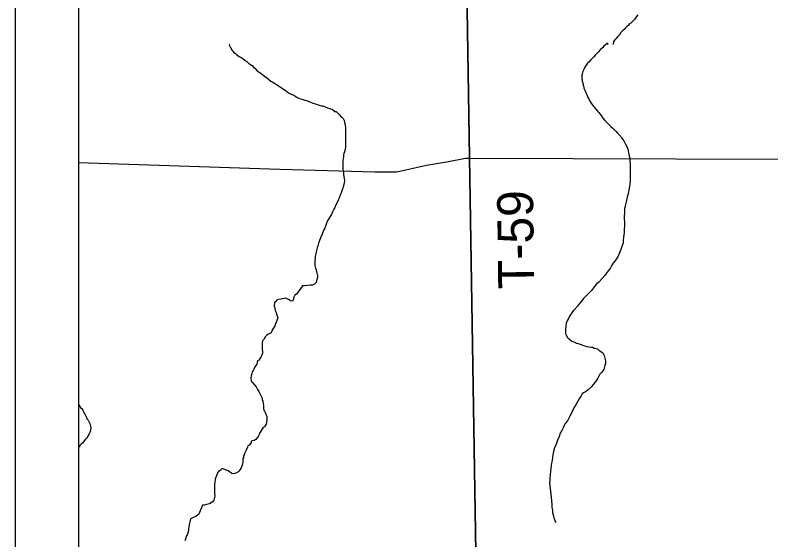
# Model space of a CAD drawing. Extents: x 0 to 34, y 0 to 22.
# Drawn here: x 2 to 3.195, y 17.112 to 17.941 of the extents above; entities that cross this region are included whole.
import ezdxf

# ---------------------------------------------------------------- set-up
doc = ezdxf.new("R2010")
doc.units = 0
for name, color, linetype in [('GM_X_Corporation', 7, 'Continuous'), ('GM_X_Minor_River', 7, 'Continuous'), ('GM_X_Township_Road', 7, 'Continuous'), ('GM_X_Township_Road_Text', 7, 'Continuous'), ('GM_X_US_Route', 7, 'Continuous'), ('SH_Data', 7, 'Continuous')]:
    doc.layers.add(name, color=color, linetype=linetype)

msp = doc.modelspace()

# ---------------------------------------------------------------- linework, layer by layer
at = {"layer": 'GM_X_Corporation'}
for points in [[(3.1996, 20.2345), (3.1561, 20.2337), (3.1064, 20.2336), (3.0286, 20.2331), (3.0007, 20.2328), (2.9354, 20.2326), (2.8825, 20.2322), (2.8234, 20.2319), (2.7333, 20.2317), (2.6825, 20.2316), (2.6344, 20.2324), (2.5847, 20.2334), (2.535, 20.2346), (2.5164, 20.2351), (2.4604, 20.2364), (2.3921, 20.2383), (2.333, 20.2398), (2.2833, 20.2411), (2.246, 20.2419), (2.187, 20.2434), (2.1124, 20.2453), (2.1, 20.2456), (2.1, 14.1)], [(3.1996, 20.2345), (3.1561, 20.2337), (3.1064, 20.2336), (3.0286, 20.2331), (3.0007, 20.2328), (2.9354, 20.2326), (2.8825, 20.2322), (2.8234, 20.2319), (2.7333, 20.2317), (2.6825, 20.2316), (2.6883, 19.5017), (2.7024, 18.7188), (2.7184, 17.7156), (2.7304, 16.9599), (2.7477, 15.8824), (2.7366, 15.2014)]]:
    msp.add_lwpolyline(points, dxfattribs=at)
msp.add_lwpolyline([(2.1, 20.2456), (2.1, 15.2121), (2.7366, 15.2014), (2.7477, 15.8824), (2.7304, 16.9599), (2.7184, 17.7156), (2.7024, 18.7188), (2.6883, 19.5017), (2.6825, 20.2316), (2.6344, 20.2324), (2.5847, 20.2334), (2.535, 20.2346), (2.5164, 20.2351), (2.4604, 20.2364), (2.3921, 20.2383), (2.333, 20.2398), (2.2833, 20.2411), (2.246, 20.2419), (2.187, 20.2434), (2.1124, 20.2453)], close=True, dxfattribs=at)
at = {"layer": 'GM_X_Minor_River'}
for points in [[(2.9845, 17.9415), (2.9822, 17.9384), (2.9791, 17.9339), (2.9757, 17.9301), (2.9734, 17.9282), (2.9715, 17.927), (2.9693, 17.9244), (2.9666, 17.9221), (2.9647, 17.9206), (2.9632, 17.9187), (2.9605, 17.9164), (2.9578, 17.9134), (2.9552, 17.9099), (2.9529, 17.9069), (2.9499, 17.9035), (2.9483, 17.9016), (2.9461, 17.8989), (2.9453, 17.8942)], [(2.3393, 17.8938), (2.3386, 17.8937), (2.3404, 17.8895), (2.3431, 17.8849), (2.3457, 17.8818), (2.3483, 17.8803), (2.3502, 17.8787), (2.3543, 17.8756), (2.3574, 17.8737), (2.36, 17.8722), (2.363, 17.8695), (2.3664, 17.8675), (2.369, 17.8648), (2.3721, 17.8629), (2.3747, 17.861), (2.3769, 17.8587), (2.3792, 17.8571), (2.3826, 17.8529), (2.386, 17.8509), (2.3886, 17.849), (2.3909, 17.8471), (2.3939, 17.8448), (2.3973, 17.8421), (2.4007, 17.8394), (2.4041, 17.8367), (2.4075, 17.8347), (2.4101, 17.8332), (2.4131, 17.8312), (2.4165, 17.8293), (2.4271, 17.8223), (2.432, 17.8181), (2.4373, 17.8154), (2.4407, 17.8142), (2.4437, 17.8122), (2.4459, 17.8107), (2.4497, 17.8091), (2.4531, 17.808), (2.4565, 17.8068), (2.4615, 17.8052), (2.466, 17.8036), (2.4709, 17.8017), (2.4762, 17.8001), (2.4808, 17.7985), (2.4842, 17.7977), (2.4865, 17.7973), (2.4914, 17.7953), (2.4952, 17.7938), (2.4986, 17.793), (2.5012, 17.7922), (2.5057, 17.7887), (2.5076, 17.7883), (2.5103, 17.786), (2.5129, 17.7833), (2.5144, 17.7814), (2.5163, 17.7798), (2.5185, 17.7775), (2.52, 17.7741), (2.5207, 17.7714), (2.5215, 17.7695), (2.5218, 17.7661), (2.5222, 17.7638), (2.5225, 17.7585), (2.5225, 17.7558), (2.5224, 17.7524), (2.5223, 17.7471), (2.5223, 17.7421), (2.5222, 17.7372), (2.5222, 17.733), (2.5217, 17.7285), (2.5209, 17.7247), (2.5198, 17.7224), (2.5194, 17.7201), (2.5189, 17.7171), (2.5185, 17.714), (2.5181, 17.7114), (2.5181, 17.7076), (2.518, 17.7046), (2.518, 17.7007), (2.5183, 17.6988), (2.5183, 17.6969), (2.5187, 17.6947), (2.519, 17.6916), (2.5194, 17.6886), (2.5197, 17.6859), (2.5204, 17.6829), (2.5208, 17.6802), (2.5208, 17.6783), (2.5204, 17.676), (2.5199, 17.6734), (2.5188, 17.6696), (2.518, 17.6673), (2.5172, 17.665), (2.516, 17.6616), (2.5148, 17.6586), (2.5137, 17.6563), (2.5129, 17.6544), (2.5121, 17.6518), (2.5105, 17.6484), (2.509, 17.645), (2.507, 17.6408), (2.5054, 17.637)], [(2.937, 17.8942), (2.937, 17.8972), (2.9355, 17.8954), (2.9332, 17.8939), (2.9305, 17.8916), (2.9285, 17.8894), (2.9251, 17.886), (2.9224, 17.8826), (2.9197, 17.88), (2.917, 17.8773), (2.9147, 17.8747), (2.9124, 17.8721), (2.9097, 17.8694), (2.9074, 17.8672), (2.9051, 17.8649), (2.9027, 17.8619), (2.9016, 17.86), (2.8996, 17.857), (2.8989, 17.8547), (2.8977, 17.8517), (2.8969, 17.8494), (2.8961, 17.8457), (2.8961, 17.843), (2.896, 17.8403), (2.8964, 17.8384), (2.8967, 17.8361), (2.8978, 17.8323), (2.8982, 17.8297), (2.8989, 17.8274), (2.8993, 17.8255), (2.9004, 17.8224), (2.9041, 17.8136), (2.9056, 17.8106), (2.907, 17.8083), (2.9085, 17.8048), (2.9119, 17.8002), (2.9153, 17.7952), (2.9186, 17.7918), (2.9209, 17.7891), (2.9228, 17.7868), (2.9246, 17.7849), (2.9265, 17.7822), (2.9291, 17.778), (2.9325, 17.7745), (2.9355, 17.7711), (2.9381, 17.7687), (2.9419, 17.7649), (2.9453, 17.7618), (2.9479, 17.7591), (2.9501, 17.7568), (2.9524, 17.7541), (2.9554, 17.7511), (2.9577, 17.7488), (2.9588, 17.7468), (2.9606, 17.7445), (2.9621, 17.7422), (2.9633, 17.7403), (2.9647, 17.7369), (2.967, 17.7334), (2.9677, 17.7315), (2.9684, 17.7289), (2.9692, 17.7266), (2.9695, 17.7239), (2.9703, 17.7216), (2.971, 17.7182), (2.9717, 17.7151), (2.972, 17.7125), (2.972, 17.7102), (2.9723, 17.7056), (2.9723, 17.7007), (2.9721, 17.6897), (2.9721, 17.6859), (2.9724, 17.6828), (2.9724, 17.6786), (2.972, 17.6741), (2.9715, 17.6699), (2.9703, 17.665), (2.9695, 17.6608), (2.9687, 17.6566), (2.9675, 17.6532), (2.9663, 17.6479), (2.9655, 17.6437), (2.9643, 17.6396), (2.9639, 17.6369), (2.9635, 17.635), (2.9635, 17.632), (2.9634, 17.6274), (2.963, 17.6236), (2.963, 17.6206), (2.9629, 17.6172), (2.9633, 17.6153), (2.9632, 17.6122), (2.9632, 17.6092), (2.9632, 17.6069), (2.9631, 17.6039), (2.9627, 17.6012), (2.9627, 17.597), (2.9623, 17.5936), (2.9618, 17.5898), (2.9614, 17.5849), (2.961, 17.5807)], [(2.5054, 17.637), (2.5039, 17.6344), (2.5019, 17.6302), (2.5, 17.6257), (2.4946, 17.617), (2.4934, 17.6148), (2.4922, 17.6121), (2.491, 17.6083), (2.4895, 17.6042), (2.4879, 17.6015), (2.4867, 17.5977), (2.4848, 17.5939), (2.4832, 17.5898), (2.4812, 17.5845), (2.4797, 17.5803), (2.4785, 17.5765), (2.4773, 17.5731), (2.4765, 17.569), (2.4757, 17.5659), (2.4753, 17.564), (2.4749, 17.5621), (2.4745, 17.5595), (2.4741, 17.5564), (2.474, 17.5526), (2.4736, 17.5496), (2.4736, 17.5473), (2.4739, 17.5454), (2.4743, 17.5431), (2.475, 17.5408), (2.4757, 17.5382), (2.4765, 17.5359), (2.4772, 17.5332), (2.4776, 17.5309), (2.4779, 17.5286), (2.4779, 17.5264), (2.4771, 17.523), (2.4767, 17.5211), (2.4759, 17.5184), (2.4732, 17.5158), (2.4701, 17.5143), (2.4667, 17.514), (2.4621, 17.5136), (2.4576, 17.5129), (2.4545, 17.513), (2.4449, 17.5001), (2.4422, 17.4983), (2.4406, 17.4953), (2.4402, 17.4934), (2.4394, 17.4907), (2.4383, 17.4888), (2.4356, 17.4892), (2.4322, 17.4912), (2.4292, 17.4931), (2.4273, 17.4935), (2.4208, 17.4921), (2.4163, 17.4914), (2.414, 17.491), (2.4128, 17.4884), (2.4101, 17.4865), (2.4097, 17.4808), (2.4104, 17.4785), (2.4108, 17.4766), (2.4111, 17.4747), (2.4119, 17.4728), (2.4126, 17.4709), (2.4133, 17.4686), (2.4144, 17.4659), (2.4152, 17.4625), (2.414, 17.4583), (2.4128, 17.4553), (2.4116, 17.4534), (2.4104, 17.45), (2.4077, 17.4455), (2.4062, 17.4432), (2.4046, 17.4387), (2.4004, 17.4368), (2.3981, 17.4349), (2.3958, 17.4331), (2.3931, 17.4282), (2.3911, 17.4259), (2.3903, 17.4229), (2.3903, 17.4206), (2.3903, 17.4164), (2.3906, 17.4141), (2.3906, 17.4122), (2.3913, 17.4095), (2.3909, 17.4069), (2.3901, 17.4035), (2.3886, 17.4005), (2.387, 17.3978), (2.3851, 17.3956), (2.3832, 17.3944), (2.382, 17.3895), (2.3792, 17.385), (2.3773, 17.3816), (2.3761, 17.3793), (2.375, 17.3771), (2.3742, 17.374), (2.3734, 17.371), (2.3726, 17.3676), (2.3733, 17.3626)], [(2.961, 17.5807), (2.9602, 17.578), (2.9594, 17.5758), (2.9582, 17.572), (2.9566, 17.5678), (2.9551, 17.564), (2.9527, 17.5591), (2.95, 17.5554), (2.9481, 17.552), (2.9457, 17.5489), (2.9434, 17.5459), (2.9411, 17.5414), (2.938, 17.5373), (2.9353, 17.5339), (2.9322, 17.5293), (2.928, 17.5244), (2.923, 17.5188), (2.9184, 17.5154), (2.9156, 17.5113), (2.9118, 17.5064), (2.8979, 17.4925), (2.8952, 17.4887), (2.8921, 17.485), (2.889, 17.4808), (2.8844, 17.4759), (2.8821, 17.4733), (2.8802, 17.4703), (2.8783, 17.4684), (2.8763, 17.465), (2.8747, 17.4612), (2.8732, 17.459), (2.8712, 17.454), (2.8704, 17.4487), (2.87, 17.4453), (2.87, 17.443), (2.8699, 17.44), (2.8703, 17.4377), (2.871, 17.4354), (2.8729, 17.432), (2.8744, 17.4301), (2.8763, 17.4289), (2.88, 17.4258), (2.8831, 17.4246), (2.8857, 17.4235), (2.8876, 17.4227), (2.8902, 17.4219), (2.8925, 17.4211), (2.8948, 17.4203), (2.8971, 17.4191), (2.9001, 17.4183), (2.9039, 17.4172), (2.9077, 17.4164), (2.9111, 17.4159), (2.9134, 17.4159), (2.9156, 17.4147), (2.9187, 17.4139), (2.9206, 17.4135), (2.9228, 17.4116), (2.9292, 17.407), (2.9314, 17.4028), (2.9325, 17.3989), (2.9333, 17.3948), (2.9332, 17.3925), (2.9332, 17.3898), (2.9324, 17.3872), (2.9308, 17.3807), (2.9269, 17.3762), (2.9243, 17.3736), (2.9211, 17.3672), (2.9173, 17.3615), (2.9138, 17.3574), (2.9111, 17.3536), (2.9053, 17.3483), (2.9015, 17.3457), (2.8988, 17.3439), (2.8965, 17.3424), (2.8942, 17.3382), (2.8919, 17.3344), (2.8895, 17.331), (2.8872, 17.3261), (2.8845, 17.3216), (2.8822, 17.3182), (2.8802, 17.3129), (2.8767, 17.3069), (2.8732, 17.2997), (2.8697, 17.2955), (2.8682, 17.2921), (2.8662, 17.2884), (2.8643, 17.2846), (2.8619, 17.2804), (2.86, 17.2751), (2.8576, 17.2691), (2.8553, 17.263), (2.8529, 17.2573), (2.8513, 17.2513), (2.8501, 17.246), (2.8493, 17.2418), (2.8489, 17.2369), (2.8481, 17.2327), (2.8476, 17.2293), (2.8459, 17.2149)], [(2.3733, 17.3626), (2.3748, 17.3607), (2.3774, 17.3576), (2.3812, 17.3534), (2.383, 17.3492), (2.3852, 17.3461), (2.3864, 17.3438), (2.3878, 17.3408), (2.389, 17.3385), (2.3904, 17.3354), (2.3908, 17.3335), (2.3915, 17.3309), (2.3922, 17.3274), (2.3926, 17.3236), (2.3926, 17.3213), (2.3929, 17.3187), (2.3933, 17.3168), (2.394, 17.3149), (2.3955, 17.3129), (2.397, 17.3091), (2.3977, 17.3068), (2.3981, 17.3049), (2.398, 17.3004), (2.3968, 17.2947), (2.3941, 17.2905), (2.3922, 17.2894), (2.3864, 17.28), (2.3856, 17.2781), (2.3844, 17.2751), (2.3821, 17.2721), (2.3805, 17.2702), (2.3779, 17.2687), (2.3752, 17.268), (2.3733, 17.2676), (2.3732, 17.2649), (2.3702, 17.2612), (2.3679, 17.2601), (2.3675, 17.2582), (2.3655, 17.2532), (2.3632, 17.2491), (2.362, 17.2461), (2.3612, 17.2442), (2.3608, 17.2415), (2.36, 17.2396), (2.36, 17.2354), (2.3595, 17.2313), (2.3576, 17.2252), (2.3556, 17.2229), (2.3537, 17.2203), (2.3522, 17.2184), (2.3502, 17.2173), (2.3472, 17.2166), (2.3449, 17.2162), (2.3426, 17.2163), (2.337, 17.2205), (2.3324, 17.2225), (2.3287, 17.224), (2.3268, 17.224), (2.3244, 17.2214), (2.3214, 17.2199), (2.3198, 17.2177), (2.3183, 17.2127), (2.3171, 17.2105), (2.3163, 17.2074), (2.3155, 17.2025), (2.3151, 17.1999), (2.315, 17.198), (2.315, 17.1953), (2.3153, 17.1915), (2.3153, 17.1888), (2.3153, 17.185), (2.3156, 17.1808), (2.3144, 17.1744), (2.3117, 17.171), (2.3071, 17.1688), (2.3025, 17.1673), (2.2987, 17.1666), (2.296, 17.1663), (2.2902, 17.1523), (2.2882, 17.1508), (2.2848, 17.1478), (2.2794, 17.1459), (2.2771, 17.1448), (2.2763, 17.1403), (2.2755, 17.138), (2.2747, 17.1323), (2.2743, 17.1289), (2.2739, 17.1262), (2.2723, 17.1205), (2.2711, 17.1179), (2.2695, 17.1126), (2.2684, 17.1103)], [(2.1, 17.3262), (2.1025, 17.3225), (2.1036, 17.3206), (2.1063, 17.3179), (2.107, 17.316), (2.1081, 17.3141), (2.11, 17.3102), (2.1111, 17.308), (2.1126, 17.3049), (2.1141, 17.3026), (2.1156, 17.3007), (2.1167, 17.2988), (2.1182, 17.2953), (2.1189, 17.2934), (2.1192, 17.2911), (2.1196, 17.2888)], [(2.1196, 17.2888), (2.1192, 17.2854), (2.1188, 17.2831), (2.118, 17.2813), (2.1172, 17.2794), (2.116, 17.2775), (2.1149, 17.2748), (2.1133, 17.273), (2.1114, 17.2707), (2.1091, 17.2681), (2.1068, 17.265), (2.1045, 17.2628), (2.1025, 17.2605), (2.1, 17.2574)], [(2.8459, 17.2149), (2.8455, 17.2099), (2.8451, 17.2057), (2.845, 17.2016), (2.8453, 17.197), (2.846, 17.1924), (2.8464, 17.1886), (2.8471, 17.184), (2.8474, 17.1791), (2.8481, 17.1734), (2.8484, 17.1677), (2.8487, 17.1631), (2.8494, 17.1582), (2.8498, 17.1551), (2.8505, 17.1513), (2.8516, 17.1467), (2.8527, 17.1437), (2.8538, 17.1406), (2.8553, 17.1391)]]:
    msp.add_lwpolyline(points, dxfattribs=at)
at = {"layer": 'GM_X_Township_Road'}
for points in [[(2.7186, 17.715), (2.7026, 18.7182), (2.697, 19.0294)], [(2.7371, 15.2138), (2.7479, 15.8819), (2.7307, 16.9594), (2.7186, 17.715)]]:
    msp.add_lwpolyline(points, dxfattribs=at)
at = {"layer": 'GM_X_US_Route'}
for points in [[(2.7186, 17.715), (3.3704, 17.7126), (3.7523, 17.7146), (4.2798, 17.7216), (4.2949, 17.7218)], [(2.1, 17.708), (2.4183, 17.6973), (2.5689, 17.693), (2.5852, 17.6931), (2.6033, 17.6933), (2.6505, 17.7038), (2.6851, 17.7095), (2.7118, 17.715), (2.7186, 17.715)]]:
    msp.add_lwpolyline(points, dxfattribs=at)
at = {"layer": 'SH_Data'}
for p, q in [((2, 21), (2, 14)), ((2.1, 20.9), (2.1, 14.1))]:
    msp.add_line(p, q, dxfattribs=at)

# ---------------------------------------------------------------- texts
at = {"layer": 'GM_X_Township_Road_Text'}
msp.add_text('T-59', height=0.05682, rotation=90.7069, dxfattribs=at).set_placement((2.8206, 17.5083))

doc.saveas('drawing.dxf')
